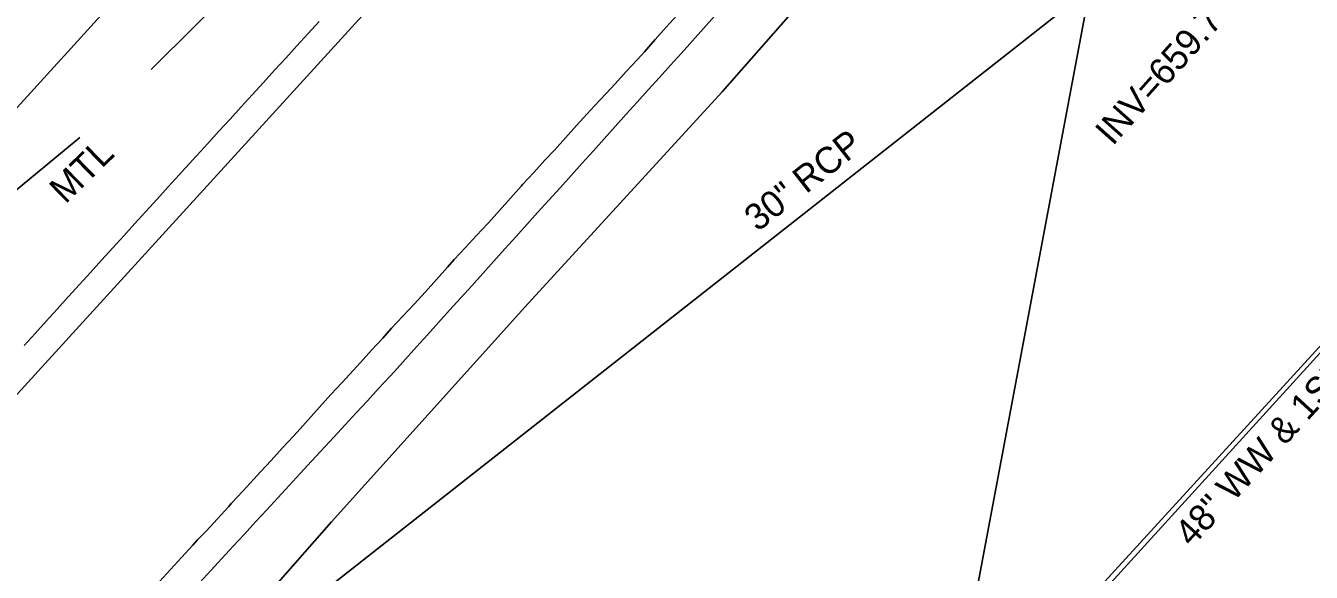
# Model space of a CAD drawing. Extents: x 1806071 to 1809844, y 912722 to 917035.
# Drawn here: x 1807955 to 1808149.9, y 914717.3 to 914800.2 of the extents above; entities that cross this region are included whole.
import ezdxf

# ---------------------------------------------------------------- set-up
doc = ezdxf.new("R2010")
doc.units = 0
for name, color, linetype in [('Exist Guardrail', 7, 'Continuous'), ('Exist Guardrail Cable Guide Rail', 7, 'Continuous'), ('Exist Guardrail Text', 7, 'Continuous'), ('Exist Horizontal Alignment', 7, 'Continuous'), ('Exist Other Culture Fence Line', 7, 'Continuous'), ('Exist Other Culture Fence Line Text', 7, 'Continuous'), ('Exist Right of Way Line', 7, 'Continuous'), ('Exist Roads EOP', 7, 'Continuous'), ('Exist Roads EOT', 7, 'Continuous'), ('Exist Structure Minor Pipes RCP 30 Inch', 7, 'Continuous'), ('Exist Structure Minor Pipes RCP 30 Inch Invert', 7, 'Continuous'), ('Exist Structure Minor Pipes RCP 30 Inch Text', 7, 'Continuous'), ('Exist Vegetation Woods Line', 7, 'Continuous')]:
    doc.layers.add(name, color=color, linetype=linetype)

msp = doc.modelspace()

# ---------------------------------------------------------------- linework, layer by layer
at = {"layer": 'Exist Guardrail'}
for points in [[(1808591.05, 915389.5), (1808569.06, 915365.7), (1808543.65, 915338.5), (1808510.12, 915301.43), (1808476.4, 915264.39), (1808442.71, 915227.63), (1808412.8, 915194.83), (1808379.91, 915158.29), (1808346.06, 915121.3), (1808316.39, 915089.09), (1808287.07, 915056.31), (1808258.76, 915023.41), (1808230.12, 914989.62), (1808202.58, 914956.19), (1808174.39, 914923.17), (1808146.14, 914889.53), (1808117.77, 914855.87), (1808088.77, 914822.19), (1808060.62, 914790.15), (1808030.71, 914757.47), (1808001.37, 914724.91), (1807974.55, 914694.38)], [(1807963.2, 914783.22), (1807935.17, 914760.04), (1807908.57, 914736.42), (1807882.27, 914710.65), (1807863.47, 914692.52), (1807840.66, 914668.07), (1807814.87, 914639.07), (1807789.47, 914611.6), (1807764.43, 914584.29), (1807738.95, 914556.51), (1807714.06, 914529.04), (1807691.49, 914504.04)]]:
    msp.add_lwpolyline(points, dxfattribs=at)
at = {"layer": 'Exist Guardrail Cable Guide Rail'}
msp.add_lwpolyline([(1807974.04, 914793.5), (1807987.44, 914806.88), (1808014.49, 914836.2), (1808046.81, 914871.43), (1808079.07, 914907.03), (1808115.43, 914946.85), (1808153.1, 914988.37), (1808190.68, 915029.49), (1808228.19, 915070.67), (1808264.68, 915110.73), (1808292.14, 915140.7), (1808316.64, 915167.2)], dxfattribs=at)
at = {"layer": 'Exist Horizontal Alignment'}
msp.add_line((1806073.69, 912724.84), (1809374.2, 916346.52), dxfattribs=at)
at = {"layer": 'Exist Other Culture Fence Line'}
msp.add_line((1808258.12, 914868.51), (1807957.39, 914539.49), dxfattribs=at)
at = {"layer": 'Exist Right of Way Line'}
msp.add_line((1808525.76, 915161.65), (1807958.27, 914538.68), dxfattribs=at)
at = {"layer": 'Exist Roads EOP'}
for points in [[(1807999.48, 914800.78), (1807997.79, 914798.93), (1807996.1, 914797.09), (1807994.42, 914795.24), (1807992.73, 914793.4), (1807991.05, 914791.55), (1807989.36, 914789.7), (1807987.67, 914787.86), (1807985.99, 914786.01), (1807984.3, 914784.17), (1807982.62, 914782.32), (1807980.93, 914780.47), (1807979.24, 914778.63), (1807978.27, 914777.56), (1807976.59, 914775.71), (1807974.91, 914773.86), (1807973.23, 914772.01), (1807971.55, 914770.16), (1807969.87, 914768.31), (1807968.19, 914766.46), (1807966.5, 914764.61), (1807964.82, 914762.76), (1807963.14, 914760.91), (1807961.46, 914759.06), (1807959.78, 914757.2), (1807958.1, 914755.35), (1807956.42, 914753.5), (1807954.74, 914751.65)], [(1807981.38, 914715.73), (1807983.07, 914717.57), (1807984.77, 914719.41), (1807986.46, 914721.25), (1807988.16, 914723.08), (1807989.85, 914724.92), (1807991.55, 914726.76), (1807993.25, 914728.59), (1807994.94, 914730.43), (1807996.64, 914732.27), (1807998.33, 914734.11), (1808001.72, 914737.78), (1808003.42, 914739.62), (1808005.11, 914741.45), (1808006.81, 914743.29), (1808008.51, 914745.13), (1808010.2, 914746.97), (1808010.91, 914747.74), (1808012.59, 914749.6), (1808014.26, 914751.45), (1808015.94, 914753.31), (1808017.61, 914755.17), (1808019.28, 914757.02), (1808020.96, 914758.88), (1808022.63, 914760.74), (1808024.31, 914762.59), (1808025.98, 914764.45), (1808027.65, 914766.31), (1808029.33, 914768.16), (1808031, 914770.02), (1808032.68, 914771.88), (1808034.35, 914773.73), (1808036.02, 914775.59), (1808037.7, 914777.45), (1808039.37, 914779.31), (1808041.04, 914781.16), (1808042.72, 914783.02), (1808044.39, 914784.88), (1808046.07, 914786.73), (1808047.74, 914788.59), (1808049.41, 914790.45), (1808051.09, 914792.3), (1808052.76, 914794.16), (1808054.44, 914796.02), (1808056.11, 914797.87), (1808057.78, 914799.73), (1808059.46, 914801.59)]]:
    msp.add_lwpolyline(points, dxfattribs=at)
at = {"layer": 'Exist Roads EOT'}
msp.add_line((1807617.6, 914375.74), (1808224.93, 915041.78), dxfattribs=at)
msp.add_lwpolyline([(1807975.27, 914715.88), (1807976.95, 914717.7), (1807978.64, 914719.54), (1807980.33, 914721.38), (1807981.06, 914722.18), (1807982.38, 914723.54), (1807984.07, 914725.38), (1807985.75, 914727.23), (1807986.21, 914727.74), (1807987.9, 914729.58), (1807989.59, 914731.42), (1807990.58, 914732.5), (1807992.22, 914734.23), (1807993.91, 914736.08), (1807995.6, 914737.92), (1807996.63, 914739.05), (1807998.29, 914740.91), (1807999.96, 914742.78), (1808001.28, 914744.25), (1808002.98, 914746.08), (1808004.68, 914747.92), (1808005.77, 914749.09), (1808007.45, 914750.95), (1808009.13, 914752.8), (1808010.48, 914754.29), (1808012.18, 914756.13), (1808013.88, 914757.96), (1808015.62, 914759.83), (1808017.29, 914761.69), (1808018.96, 914763.55), (1808019.98, 914764.69), (1808021.68, 914766.52), (1808023.38, 914768.36), (1808025.08, 914770.19), (1808025.16, 914770.28), (1808026.83, 914772.15), (1808028.49, 914774.01), (1808030.16, 914775.88), (1808030.35, 914776.09), (1808032.05, 914777.93), (1808033.74, 914779.77), (1808035.17, 914781.31), (1808036.84, 914783.17), (1808038.52, 914785.03), (1808039.57, 914786.19), (1808041.27, 914788.02), (1808042.96, 914789.86), (1808044.37, 914791.37), (1808046.06, 914793.21), (1808047.75, 914795.06), (1808048.81, 914796.21), (1808050.47, 914798.08), (1808052.14, 914799.94), (1808053.78, 914801.78)], dxfattribs=at)
at = {"layer": 'Exist Structure Minor Pipes RCP 30 Inch'}
msp.add_line((1807917.07, 914649.13), (1808125.94, 914813.29), dxfattribs=at)
at = {"layer": 'Exist Vegetation Woods Line'}
msp.add_lwpolyline([(1808108.12, 914683.23), (1808099.27, 914714.87), (1808116.08, 914804.21), (1808120.23, 914842.94), (1808559.12, 915340.21), (1808564.92, 915339.58), (1808560.84, 915316.2), (1808513.2, 915243.98), (1808463.81, 915181.71), (1808444.02, 915172.44), (1808388.95, 915106.15), (1808359.09, 915070.98), (1808353.92, 915054.91), (1808362.94, 915036.53), (1808366.74, 915015.13), (1808346.47, 914993.89), (1808341.37, 914946.67)], dxfattribs=at)

# ---------------------------------------------------------------- texts
at = {"layer": 'Exist Guardrail Text'}
msp.add_text('MTL', height=4, rotation=44.4137, dxfattribs=at).set_placement((1807961.01, 914773.02))
at = {"layer": 'Exist Other Culture Fence Line Text'}
msp.add_text('48" WW & 1SBW', height=4, rotation=47.5731, dxfattribs=at).set_placement((1808131.83, 914720.96))
at = {"layer": 'Exist Structure Minor Pipes RCP 30 Inch Invert'}
msp.add_text("INV=659.74'", height=4, rotation=48.2814, dxfattribs=at).set_placement((1808119.83, 914781.82))
at = {"layer": 'Exist Structure Minor Pipes RCP 30 Inch Text'}
msp.add_text('30" RCP', height=4, rotation=38.1662, dxfattribs=at).set_placement((1808065.99, 914768.82))

doc.saveas('drawing.dxf')
